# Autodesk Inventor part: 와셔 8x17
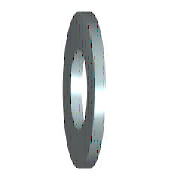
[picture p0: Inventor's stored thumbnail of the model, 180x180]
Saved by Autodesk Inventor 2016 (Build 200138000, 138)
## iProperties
IsCustomPart: 1
Created: 2012-02
Part Number: 와셔 8x17
Material: 강철, 연강
Description: 평면 와셔
Document SubType Name: Modeling
Standard: KS B 1326
Designer: mduedu
Standards Organization: KS
Language: ko-KR
Size Designation: 8x17
Categories: <MemberInstance><Categories><Category DisplayName="조임쇠" InternalName="e4da775c-781d-43d5-af7c-5136215cf5a6" Mnemonic="FSTN"><Category DisplayName="와셔" InternalN
Density: 1 g/cm^3
Appearance: 주황색
Author: mduedu
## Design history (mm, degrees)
sketch "스케치"
  geometry: C1 r 8.5 at (0, 0); C2 r 4.2 at (0, 0); 1 further point
  constraints: 2 centre point, 2 coincident
  dimensions: "d0" = 8.4 diameter of C2 (= SD1); "d1" = 17 diameter of C1 (= SD2)
extrude "본체" new body sketch "스케치" distance "d2" = 1.6 (= SD); taper "d3" = 0 deg
workaxis "Work Axis1"
workplane "Work Plane1"
body "Solid1"
other parameters: "SD1" = 8.4 [user parameter; used in 1 equation term], "SD2" = 17 [user parameter; used in 1 equation term], "SD" = 1.6 [user parameter; used in 1 equation term], "d4" = 0, "d5" = 0, "d6" = 0, "d7" = 0, "NND" = 8 [user parameter]
